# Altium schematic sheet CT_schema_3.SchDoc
size 214 x 189 mm
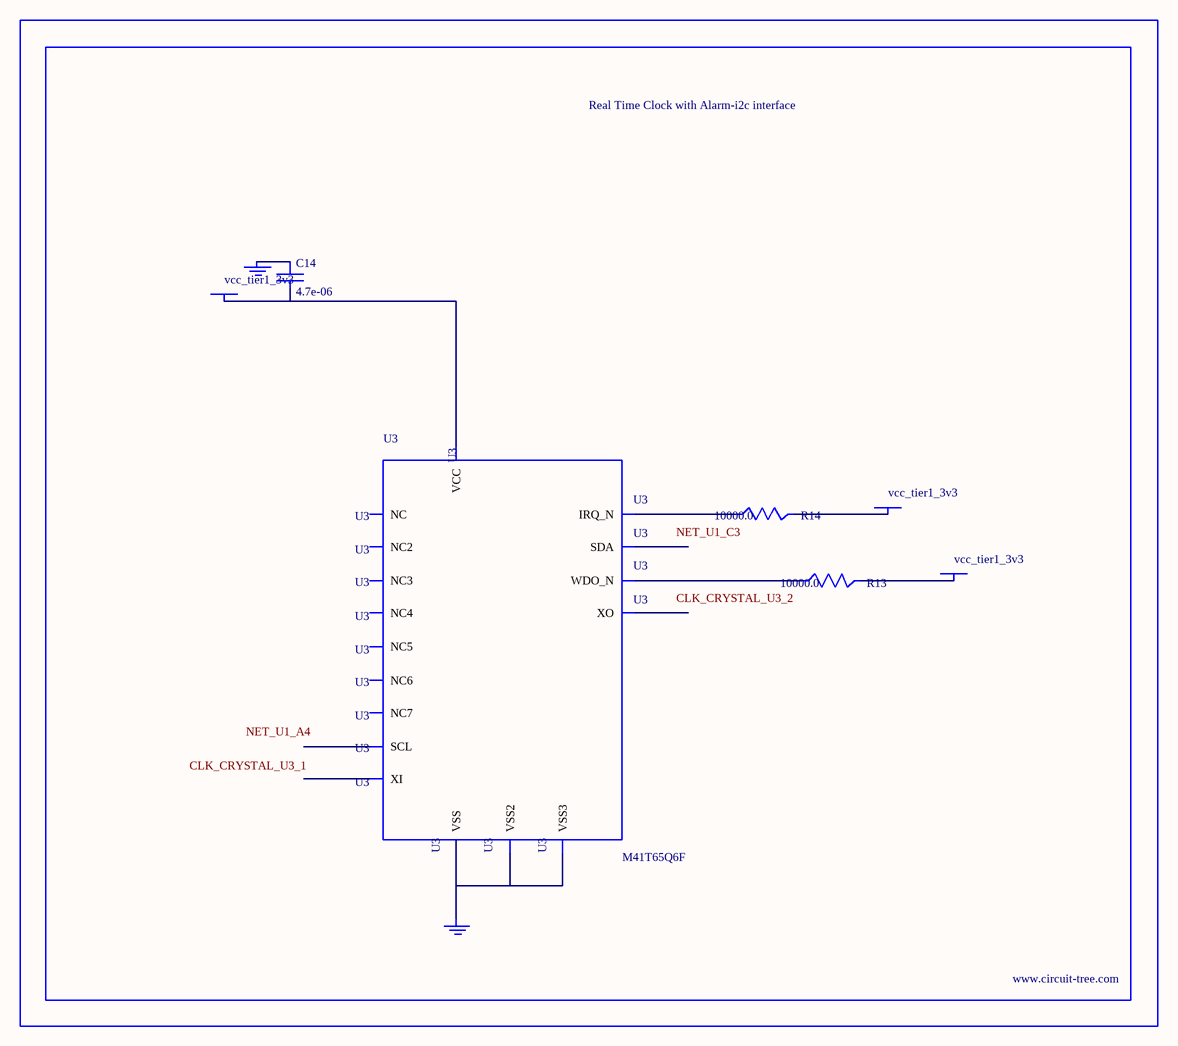
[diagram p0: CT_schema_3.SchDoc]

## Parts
BORDER2  (no value)
C14  4.7e-06  [C0805]
GND_INSTANCE_2_0  (no value)
GND_INSTANCE_2_1  (no value)
POWER_INSTANCE_2_0  vcc_tier1_3v3
POWER_INSTANCE_2_1  vcc_tier1_3v3
POWER_INSTANCE_2_2  vcc_tier1_3v3
R13  10000.0  [R0603]
R14  10000.0  [R0603]
U3  M41T65Q6F  [M41T65_QFN-16]

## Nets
NetC14_1: C14.1 GND_INSTANCE_2_0.0(GND)
NetC14_2: C14.2 POWER_INSTANCE_2_2.0(PWR) U3.14(VCC)
NetGND_INSTANCE_2_1_0: GND_INSTANCE_2_1.0(GND) U3.3(VSS) U3.5(VSS2) U3.17(VSS3)
NetPOWER_INSTANCE_2_0_0: POWER_INSTANCE_2_0.0(PWR) R13.2
NetPOWER_INSTANCE_2_1_0: POWER_INSTANCE_2_1.0(PWR) R14.2
NetR13_1: R13.1 U3.4(WDO_N)
NetR14_1: R14.1 U3.11(IRQ_N)

Not connected (* = marked no-connect by the designer): U3 1(XI) 2(XO) 6(NC) 7(NC2) 8(NC3) 9(SDA) 10(SCL) 12(NC4) 13(NC5) 15(NC6) 16(NC7)

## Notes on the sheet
- Labels drawn without touching a wire or pin: CLK_CRYSTAL_U3_1, CLK_CRYSTAL_U3_2, NET_U1_A4, NET_U1_C3

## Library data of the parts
BORDER2 = BORDER_PAGE2
C14 = C0805C475K4RACTU
GND_INSTANCE_2_0 GND_INSTANCE_2_1 = GND
POWER_INSTANCE_2_0-POWER_INSTANCE_2_2 = PWR
R13 R14 = RC0603JR-0710KL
